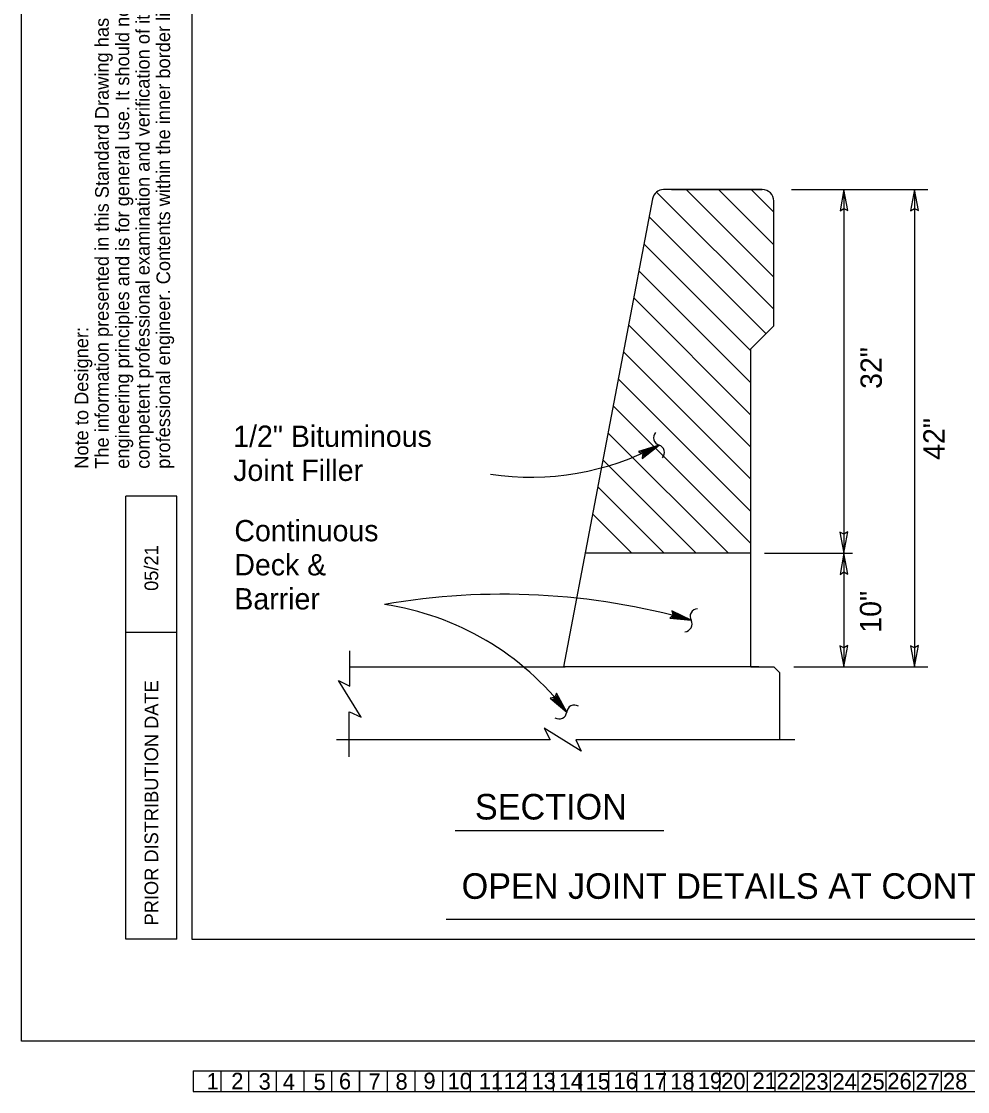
# Model space of a CAD drawing. Extents: x 0 to 2.83, y -0.03 to 1.83.
# Drawn here: x 0 to 0.578, y -0.031 to 0.623 of the extents above; entities that cross this region are included whole.
import ezdxf

# ---------------------------------------------------------------- set-up
doc = ezdxf.new("R2010")
doc.units = 0
for name, color, linetype in [('1', 7, 'Continuous'), ('10', 7, 'Continuous'), ('11', 7, 'Continuous'), ('12', 7, 'Continuous'), ('13', 7, 'Continuous'), ('14', 7, 'Continuous'), ('15', 7, 'Continuous'), ('16', 7, 'Continuous'), ('17', 7, 'Continuous'), ('18', 7, 'Continuous'), ('19', 7, 'Continuous'), ('2', 7, 'Continuous'), ('20', 7, 'Continuous'), ('21', 7, 'Continuous'), ('22', 7, 'Continuous'), ('23', 7, 'Continuous'), ('24', 7, 'Continuous'), ('25', 7, 'Continuous'), ('26', 7, 'Continuous'), ('27', 7, 'Continuous'), ('28', 7, 'Continuous'), ('3', 7, 'Continuous'), ('4', 7, 'Continuous'), ('5', 7, 'Continuous'), ('50', 7, 'Continuous'), ('54', 7, 'Continuous'), ('55', 7, 'Continuous'), ('57', 7, 'Continuous'), ('6', 7, 'Continuous'), ('62', 7, 'Continuous'), ('63', 7, 'Continuous'), ('7', 7, 'Continuous'), ('8', 7, 'Continuous'), ('9', 7, 'Continuous')]:
    doc.layers.add(name, color=color, linetype=linetype)

msp = doc.modelspace()

# ---------------------------------------------------------------- linework, layer by layer
at = {"layer": '50'}
for p, q in [((0.38824, 0.51905), (0.45983, 0.44746)), ((0.45288, 0.52057), (0.39257, 0.52057)), ((0.39733, 0.52057), (0.45288, 0.52057)), ((0.40637, 0.52057), (0.45983, 0.46711)), ((0.42601, 0.52057), (0.45983, 0.48675)), ((0.44603, 0.52057), (0.45983, 0.50677)), ((0.38574, 0.51492), (0.33135, 0.22894)), ((0.45983, 0.43723), (0.45983, 0.51362)), ((0.45983, 0.43723), (0.45983, 0.51362)), ((0.38367, 0.50398), (0.45512, 0.43253)), ((0.38053, 0.48748), (0.44594, 0.42207)), ((0.37739, 0.47098), (0.44594, 0.40243)), ((0.37425, 0.45447), (0.44594, 0.38279)), ((0.37111, 0.43797), (0.44594, 0.36314)), ((0.44594, 0.42334), (0.45983, 0.43723)), ((0.36797, 0.42147), (0.44594, 0.3435)), ((0.44594, 0.22894), (0.44594, 0.42334)), ((0.44594, 0.22894), (0.44594, 0.42334)), ((0.36483, 0.40496), (0.44594, 0.32386)), ((0.36169, 0.38846), (0.44594, 0.30422)), ((0.35855, 0.37196), (0.43213, 0.29838)), ((0.35542, 0.35546), (0.41249, 0.29838)), ((0.35228, 0.33895), (0.39285, 0.29838)), ((0.34914, 0.32245), (0.3732, 0.29838)), ((0.44594, 0.29838), (0.34456, 0.29838)), ((0.20075, 0.22894), (0.33237, 0.22894)), ((0.45074, 0.22894), (0.33135, 0.22894)), ((0.44594, 0.22894), (0.45983, 0.22894)), ((0.45983, 0.22894), (0.4633, 0.22547)), ((0.4633, 0.22547), (0.4633, 0.18431))]:
    msp.add_line(p, q, dxfattribs=at)
for centre, start, end in [((0.39257, 0.51362), 90, 169.23126), ((0.45288, 0.51362), 0, 90)]:
    msp.add_arc(centre, 0.00694, start, end, dxfattribs=at)
at = {"layer": '54'}
for points in [[(0.50275, 0.52057), (0.50038, 0.50757), (0.50275, 0.50908), (0.50515, 0.50772)], [(0.54589, 0.52061), (0.54351, 0.50762), (0.54589, 0.50912), (0.54829, 0.50777)], [(0.50275, 0.29838), (0.50513, 0.31137), (0.50275, 0.30987), (0.50035, 0.31122)], [(0.50275, 0.29838), (0.50038, 0.28539), (0.50275, 0.2869), (0.50515, 0.28554)], [(0.50275, 0.22894), (0.50513, 0.24193), (0.50275, 0.24042), (0.50035, 0.24178)], [(0.54589, 0.22894), (0.54826, 0.24193), (0.54589, 0.24042), (0.54349, 0.24178)]]:
    msp.add_lwpolyline(points, close=True, dxfattribs=at)
at = {"layer": '55'}
for p, q in [((0.47077, 0.52057), (0.5541, 0.52057)), ((0.50275, 0.52057), (0.50275, 0.29838)), ((0.54589, 0.52061), (0.54589, 0.22894)), ((0.45431, 0.29838), (0.50809, 0.29838)), ((0.20075, 0.21704), (0.20075, 0.23868)), ((0.47212, 0.22894), (0.5541, 0.22894)), ((0.2077, 0.19804), (0.19375, 0.22054)), ((0.19375, 0.22054), (0.20075, 0.21704)), ((0.20044, 0.1738), (0.20044, 0.20128)), ((0.20052, 0.20128), (0.2077, 0.19804)), ((0.34211, 0.17735), (0.3196, 0.19131)), ((0.3196, 0.19131), (0.32311, 0.18431)), ((0.32311, 0.18431), (0.19258, 0.18431)), ((0.4727, 0.18431), (0.33897, 0.18431)), ((0.33897, 0.18431), (0.34211, 0.17735))]:
    msp.add_line(p, q, dxfattribs=at)
for points in [[(0.38975, 0.36443), (0.37723, 0.36043), (0.37913, 0.35932), (0.38709, 0.363), (0.37958, 0.35842), (0.37945, 0.35623), (0.38973, 0.36441)], [(0.38523, 0.36265), (0.3795, 0.3599), (0.37853, 0.36039), (0.38847, 0.36375), (0.38014, 0.35736), (0.38028, 0.35846), (0.38555, 0.36151)], [(0.50275, 0.29838), (0.50275, 0.22894)], [(0.40937, 0.25732), (0.39757, 0.26312), (0.39817, 0.261), (0.40646, 0.25814), (0.39787, 0.26004), (0.39626, 0.25855), (0.40934, 0.25732)], [(0.40488, 0.25917), (0.39884, 0.26116), (0.39848, 0.26218), (0.40797, 0.25772), (0.39754, 0.25889), (0.3984, 0.25959), (0.40431, 0.25813)], [(0.33333, 0.20121), (0.32698, 0.21272), (0.32627, 0.21064), (0.33142, 0.20354), (0.32547, 0.21002), (0.32329, 0.20973), (0.33331, 0.20122)], [(0.33072, 0.2053), (0.32691, 0.21038), (0.3272, 0.21143), (0.33242, 0.20233), (0.32454, 0.20927), (0.32565, 0.20935), (0.32966, 0.20476)]]:
    msp.add_lwpolyline(points, dxfattribs=at)
for centre, radius, start, end in [((0.39108, 0.36891), 0.0047, 136.93703, 253.3431), ((0.31121, 0.51181), 0.16701, 261.55465, 298.04504), ((0.38839, 0.35991), 0.0047, 316.93703, 73.3431), ((0.29459, -0.14827), 0.42151, 74.20251, 99.93768), ((0.19721, 0.09771), 0.17099, 37.25404, 81.71543), ((0.41343, 0.25963), 0.0047, 93.07571, 209.48178), ((0.40525, 0.25501), 0.0047, 273.07571, 29.48178), ((0.33799, 0.20077), 0.0047, 58.11455, 174.52062), ((0.32864, 0.20167), 0.0047, 238.11455, 354.52062)]:
    msp.add_arc(centre, radius, start, end, dxfattribs=at)
at = {"layer": '57'}
for p, q in [((0.26521, 0.12877), (0.39261, 0.12877)), ((0.25962, 0.0746), (0.85699, 0.0746))]:
    msp.add_line(p, q, dxfattribs=at)
at = {"layer": '62'}
for p, q in [((0.10494, -0.01804), (1.17174, -0.01804)), ((0.10494, -0.01804), (0.10494, -0.03074)), ((0.10496, -0.0181), (1.17175, -0.0181)), ((0.10496, -0.0181), (0.10496, -0.0308)), ((0.12188, -0.01804), (0.12188, -0.03074)), ((0.12189, -0.0181), (0.12189, -0.0308)), ((0.13881, -0.01804), (0.13881, -0.03074)), ((0.13882, -0.0181), (0.13882, -0.0308)), ((0.15574, -0.01804), (0.15574, -0.03074)), ((0.15576, -0.0181), (0.15576, -0.0308)), ((0.17267, -0.01804), (0.17267, -0.03074)), ((0.17269, -0.0181), (0.17269, -0.0308)), ((0.18961, -0.01804), (0.18961, -0.03074)), ((0.18962, -0.0181), (0.18962, -0.0308)), ((0.20654, -0.01804), (0.20654, -0.03074)), ((0.20656, -0.0181), (0.20656, -0.0308)), ((0.22348, -0.01804), (0.22348, -0.03074)), ((0.22349, -0.0181), (0.22349, -0.0308)), ((0.24041, -0.01804), (0.24041, -0.03074)), ((0.24042, -0.0181), (0.24042, -0.0308)), ((0.25734, -0.01804), (0.25734, -0.03074)), ((0.25736, -0.0181), (0.25736, -0.0308)), ((0.27427, -0.01804), (0.27427, -0.03074)), ((0.27429, -0.0181), (0.27429, -0.0308)), ((0.29121, -0.01804), (0.29121, -0.03074)), ((0.29122, -0.0181), (0.29122, -0.0308)), ((0.30814, -0.01804), (0.30814, -0.03074)), ((0.30816, -0.0181), (0.30816, -0.0308)), ((0.32508, -0.01804), (0.32508, -0.03074)), ((0.32509, -0.0181), (0.32509, -0.0308)), ((0.34201, -0.01804), (0.34201, -0.03074)), ((0.34202, -0.0181), (0.34202, -0.0308)), ((0.35894, -0.01804), (0.35894, -0.03074)), ((0.35896, -0.0181), (0.35896, -0.0308)), ((0.37588, -0.01804), (0.37588, -0.03074)), ((0.37589, -0.0181), (0.37589, -0.0308)), ((0.39281, -0.01804), (0.39281, -0.03074)), ((0.39282, -0.0181), (0.39282, -0.0308)), ((0.40974, -0.01804), (0.40974, -0.03074)), ((0.40976, -0.0181), (0.40976, -0.0308)), ((0.42668, -0.01804), (0.42668, -0.03074)), ((0.42669, -0.0181), (0.42669, -0.0308)), ((0.44361, -0.01804), (0.44361, -0.03074)), ((0.44362, -0.0181), (0.44362, -0.0308)), ((0.46054, -0.01804), (0.46054, -0.03074)), ((0.46056, -0.0181), (0.46056, -0.0308)), ((0.47748, -0.01804), (0.47748, -0.03074)), ((0.47749, -0.0181), (0.47749, -0.0308)), ((0.49441, -0.01804), (0.49441, -0.03074)), ((0.49442, -0.0181), (0.49442, -0.0308)), ((0.51134, -0.01804), (0.51134, -0.03074)), ((0.51136, -0.0181), (0.51136, -0.0308)), ((0.52828, -0.01804), (0.52828, -0.03074)), ((0.52829, -0.0181), (0.52829, -0.0308)), ((0.54521, -0.01804), (0.54521, -0.03074)), ((0.54522, -0.0181), (0.54522, -0.0308)), ((0.56214, -0.01804), (0.56214, -0.03074)), ((0.56216, -0.0181), (0.56216, -0.0308)), ((0.10494, -0.03074), (1.17174, -0.03074)), ((0.10496, -0.0308), (1.17175, -0.0308))]:
    msp.add_line(p, q, dxfattribs=at)
at = {"layer": '63'}
for p, q in [((0, 0), (0, 1.83333)), ((0.06381, 0.06244), (0.06381, 0.33328)), ((0.09506, 0.33328), (0.06381, 0.33328)), ((0.09506, 0.06244), (0.09506, 0.33328)), ((0.09506, 0.24994), (0.06381, 0.24994)), ((0.09506, 0.06244), (0.06381, 0.06244)), ((2.83333, 0), (0, 0))]:
    msp.add_line(p, q, dxfattribs=at)
msp.add_lwpolyline([(2.72918, 1.77077), (0.10418, 1.77077), (0.10418, 0.06244), (2.72918, 0.06244)], close=True, dxfattribs=at)

# ---------------------------------------------------------------- texts
at = {"layer": '1'}
for p in [(0.11316, -0.02944), (0.11317, -0.02949)]:
    msp.add_text('1', height=0.01, rotation=360, dxfattribs=at).set_placement(p)
at = {"layer": '10'}
for p in [(0.26046, -0.02928), (0.26047, -0.02934)]:
    msp.add_text('10', height=0.01, rotation=360, dxfattribs=at).set_placement(p)
at = {"layer": '11'}
for p in [(0.2796, -0.02937), (0.27961, -0.02942)]:
    msp.add_text('11', height=0.01, rotation=360, dxfattribs=at).set_placement(p)
at = {"layer": '12'}
for p in [(0.29469, -0.02925), (0.29471, -0.0293)]:
    msp.add_text('12', height=0.01, rotation=360, dxfattribs=at).set_placement(p)
at = {"layer": '13'}
for p in [(0.31181, -0.02928), (0.31182, -0.02933)]:
    msp.add_text('13', height=0.01, rotation=360, dxfattribs=at).set_placement(p)
at = {"layer": '14'}
for p in [(0.32844, -0.02939), (0.32846, -0.02944)]:
    msp.add_text('14', height=0.01, rotation=360, dxfattribs=at).set_placement(p)
at = {"layer": '15'}
for p in [(0.34488, -0.02946), (0.34489, -0.02951)]:
    msp.add_text('15', height=0.01, rotation=360, dxfattribs=at).set_placement(p)
at = {"layer": '16'}
for p in [(0.3619, -0.02918), (0.36191, -0.02923)]:
    msp.add_text('16', height=0.01, rotation=360, dxfattribs=at).set_placement(p)
at = {"layer": '17'}
for p in [(0.3797, -0.02946), (0.37971, -0.02951)]:
    msp.add_text('17', height=0.01, rotation=360, dxfattribs=at).set_placement(p)
at = {"layer": '18'}
for p in [(0.39663, -0.02938), (0.39664, -0.02943)]:
    msp.add_text('18', height=0.01, rotation=360, dxfattribs=at).set_placement(p)
at = {"layer": '19'}
for p in [(0.4134, -0.02918), (0.41342, -0.02923)]:
    msp.add_text('19', height=0.01, rotation=360, dxfattribs=at).set_placement(p)
at = {"layer": '2'}
for p in [(0.12828, -0.02928), (0.12829, -0.02934)]:
    msp.add_text('2', height=0.01, rotation=360, dxfattribs=at).set_placement(p)
at = {"layer": '20'}
for p in [(0.42774, -0.02926), (0.42776, -0.02931)]:
    msp.add_text('20', height=0.01, rotation=360, dxfattribs=at).set_placement(p)
at = {"layer": '21'}
for p in [(0.44688, -0.02909), (0.44689, -0.02914)]:
    msp.add_text('21', height=0.01, rotation=360, dxfattribs=at).set_placement(p)
at = {"layer": '22'}
for p in [(0.46158, -0.02929), (0.46159, -0.02934)]:
    msp.add_text('22', height=0.01, rotation=360, dxfattribs=at).set_placement(p)
at = {"layer": '23'}
for p in [(0.47852, -0.02958), (0.47853, -0.02963)]:
    msp.add_text('23', height=0.01, rotation=360, dxfattribs=at).set_placement(p)
at = {"layer": '24'}
for p in [(0.49576, -0.02958), (0.49577, -0.02963)]:
    msp.add_text('24', height=0.01, rotation=360, dxfattribs=at).set_placement(p)
at = {"layer": '25'}
for p in [(0.51281, -0.02958), (0.51282, -0.02963)]:
    msp.add_text('25', height=0.01, rotation=360, dxfattribs=at).set_placement(p)
at = {"layer": '26'}
for p in [(0.52931, -0.02936), (0.52932, -0.02941)]:
    msp.add_text('26', height=0.01, rotation=360, dxfattribs=at).set_placement(p)
at = {"layer": '27'}
for p in [(0.54648, -0.02958), (0.54649, -0.02963)]:
    msp.add_text('27', height=0.01, rotation=360, dxfattribs=at).set_placement(p)
at = {"layer": '28'}
for p in [(0.56333, -0.02938), (0.56334, -0.02943)]:
    msp.add_text('28', height=0.01, rotation=360, dxfattribs=at).set_placement(p)
at = {"layer": '3'}
for p in [(0.145, -0.02955), (0.14501, -0.02961)]:
    msp.add_text('3', height=0.01, rotation=360, dxfattribs=at).set_placement(p)
at = {"layer": '4'}
for p in [(0.15973, -0.02984), (0.15975, -0.0299)]:
    msp.add_text('4', height=0.01, rotation=360, dxfattribs=at).set_placement(p)
at = {"layer": '5'}
for p in [(0.17858, -0.02977), (0.17859, -0.02982)]:
    msp.add_text('5', height=0.01, rotation=360, dxfattribs=at).set_placement(p)
at = {"layer": '57'}
for s, p in [('32"', (0.52591, 0.39875)), ('42"', (0.56429, 0.3554)), ('10"', (0.52555, 0.24974))]:
    msp.add_text(s, height=0.013021, rotation=90, dxfattribs=at).set_placement(p)
for s, height, p in [('1/2" Bituminous', 0.0130208, (0.12949, 0.36332)), ('Joint Filler', 0.0130208, (0.12949, 0.34249)), ('Continuous ', 0.0130208, (0.13018, 0.3056)), ('Deck & ', 0.013021, (0.13018, 0.28476)), ('Barrier', 0.013021, (0.13018, 0.26393)), ('SECTION', 0.015625, (0.2772, 0.13553)), ('OPEN JOINT DETAILS AT CONTINUOUS PIERS', 0.015625, (0.26909, 0.08704))]:
    msp.add_text(s, height=height, dxfattribs=at).set_placement(p)
at = {"layer": '6'}
for p in [(0.19409, -0.02938), (0.19411, -0.02943)]:
    msp.add_text('6', height=0.01, rotation=360, dxfattribs=at).set_placement(p)
at = {"layer": '62'}
for s, height, p in [('The information presented in this Standard Drawing has been prepared in accordance with recognized', 0.0083333, (0.05339, 0.34994)), ('competent professional examination and verification of its suitability and applicability by a licensed', 0.00833333, (0.07839, 0.34994)), ('engineering principles and is for general use. It should not be used for specific application without', 0.00833333, (0.06589, 0.34994)), ('professional engineer. Contents within the inner border line shall not be altered.', 0.0083333, (0.09089, 0.34994)), ('Note to Designer:', 0.0083333, (0.04089, 0.34994))]:
    msp.add_text(s, height=height, rotation=90, dxfattribs=at).set_placement(p)
at = {"layer": '63'}
for s, height, p in [('05/21', 0.008333, (0.0836, 0.27529)), ('PRIOR DISTRIBUTION DATE', 0.0083333, (0.0836, 0.07078))]:
    msp.add_text(s, height=height, rotation=90, dxfattribs=at).set_placement(p)
at = {"layer": '7'}
for p in [(0.21211, -0.02964), (0.21212, -0.02969)]:
    msp.add_text('7', height=0.01, rotation=360, dxfattribs=at).set_placement(p)
at = {"layer": '8'}
for p in [(0.22865, -0.02958), (0.22866, -0.02963)]:
    msp.add_text('8', height=0.01, rotation=360, dxfattribs=at).set_placement(p)
at = {"layer": '9'}
for p in [(0.24573, -0.02921), (0.24574, -0.02926)]:
    msp.add_text('9', height=0.01, rotation=360, dxfattribs=at).set_placement(p)

doc.saveas('drawing.dxf')
